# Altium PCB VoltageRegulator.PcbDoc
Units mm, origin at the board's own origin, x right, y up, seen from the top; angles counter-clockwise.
Board outline 49.88 x 50.04 mm, 2 copper layers (Top Layer, Bottom Layer); 35 components, 18 nets, 75 pads, 1 vias.
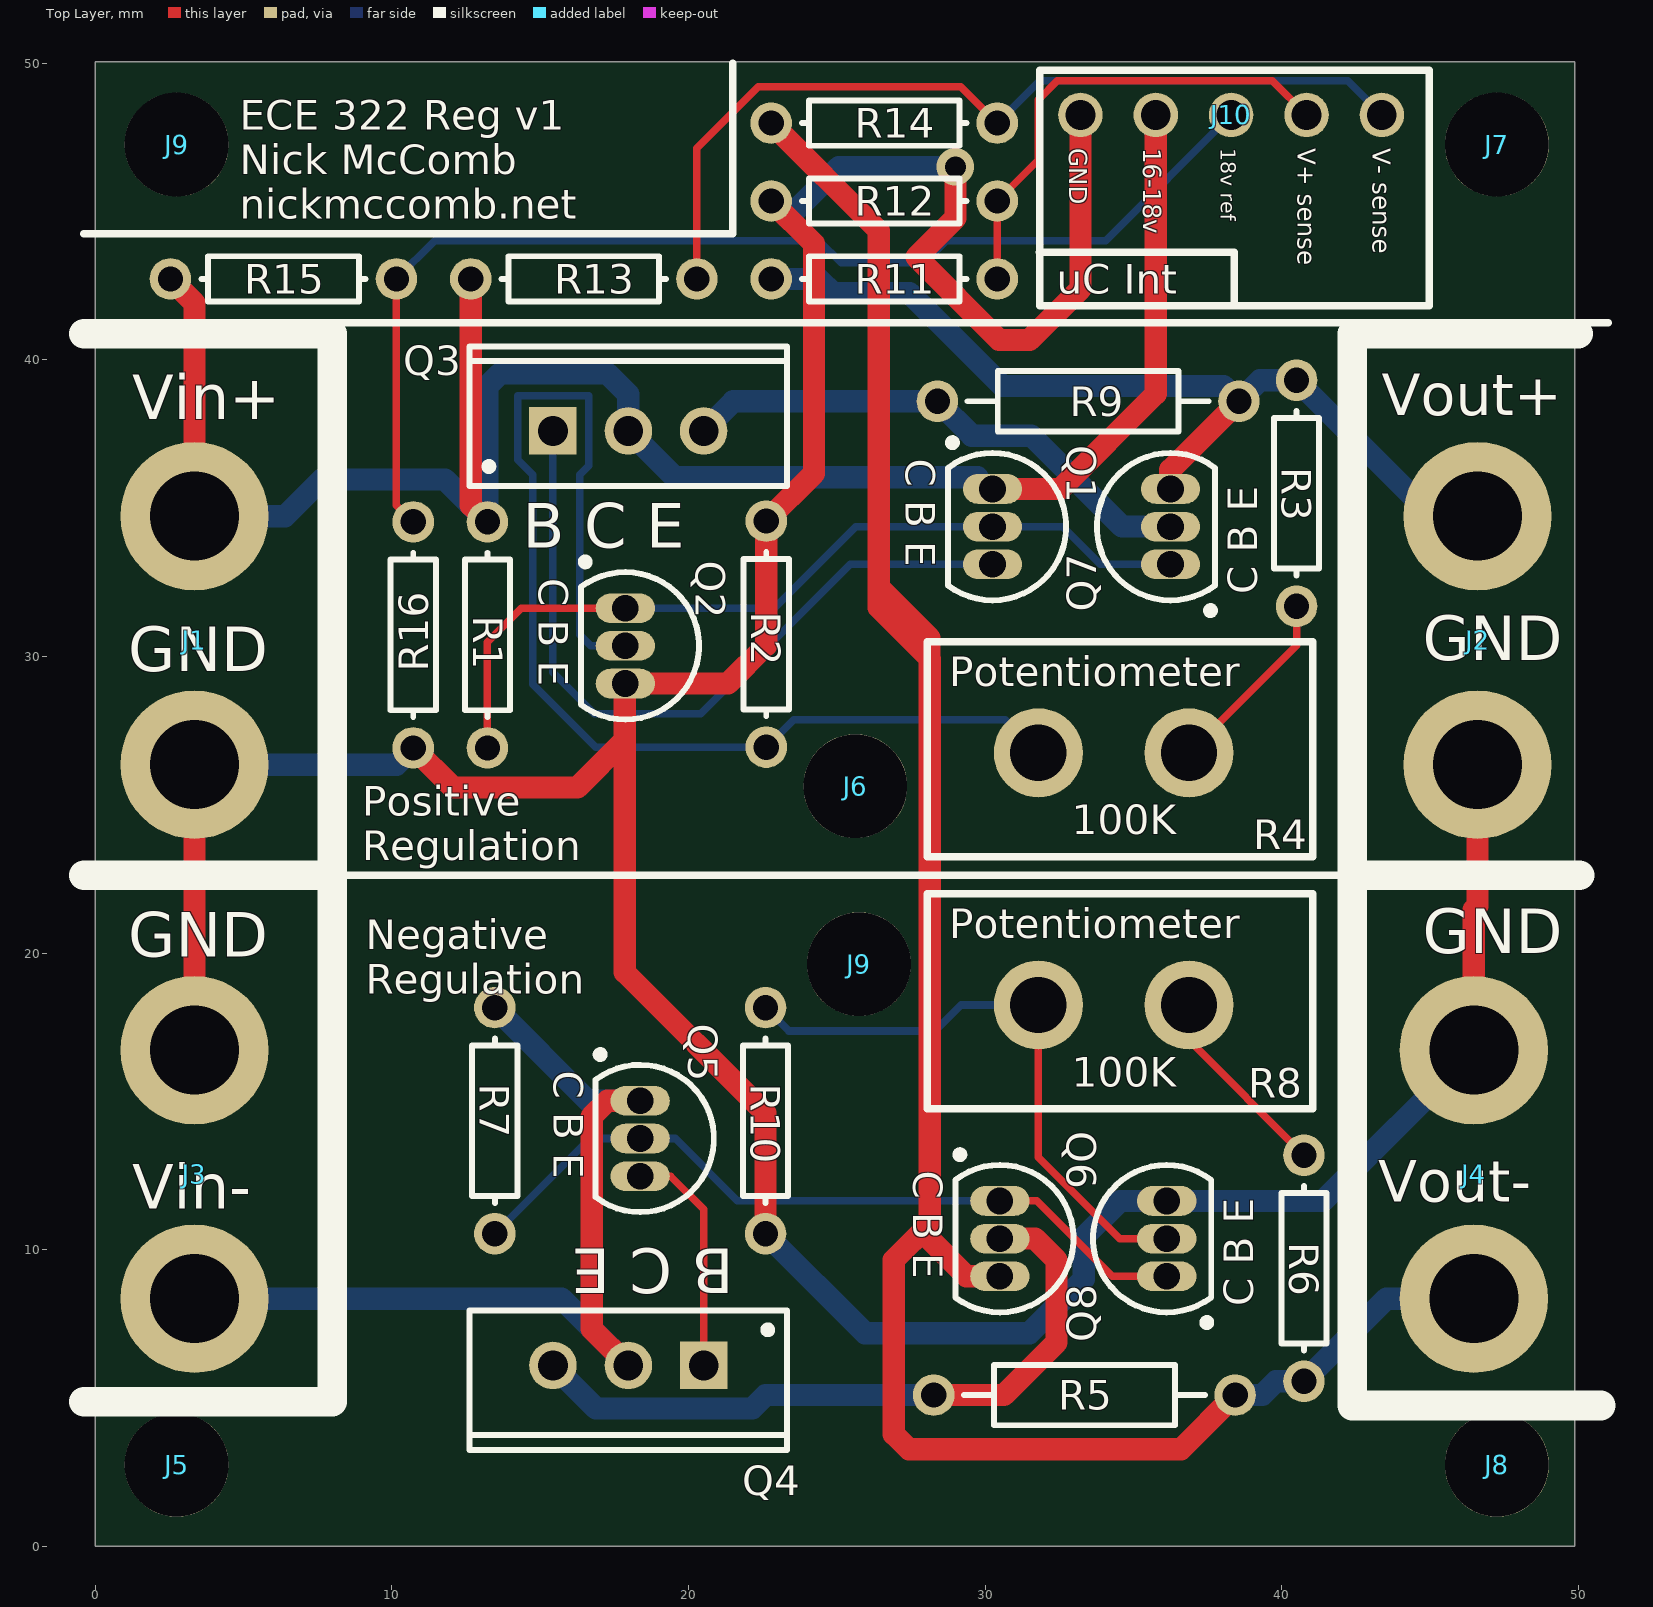
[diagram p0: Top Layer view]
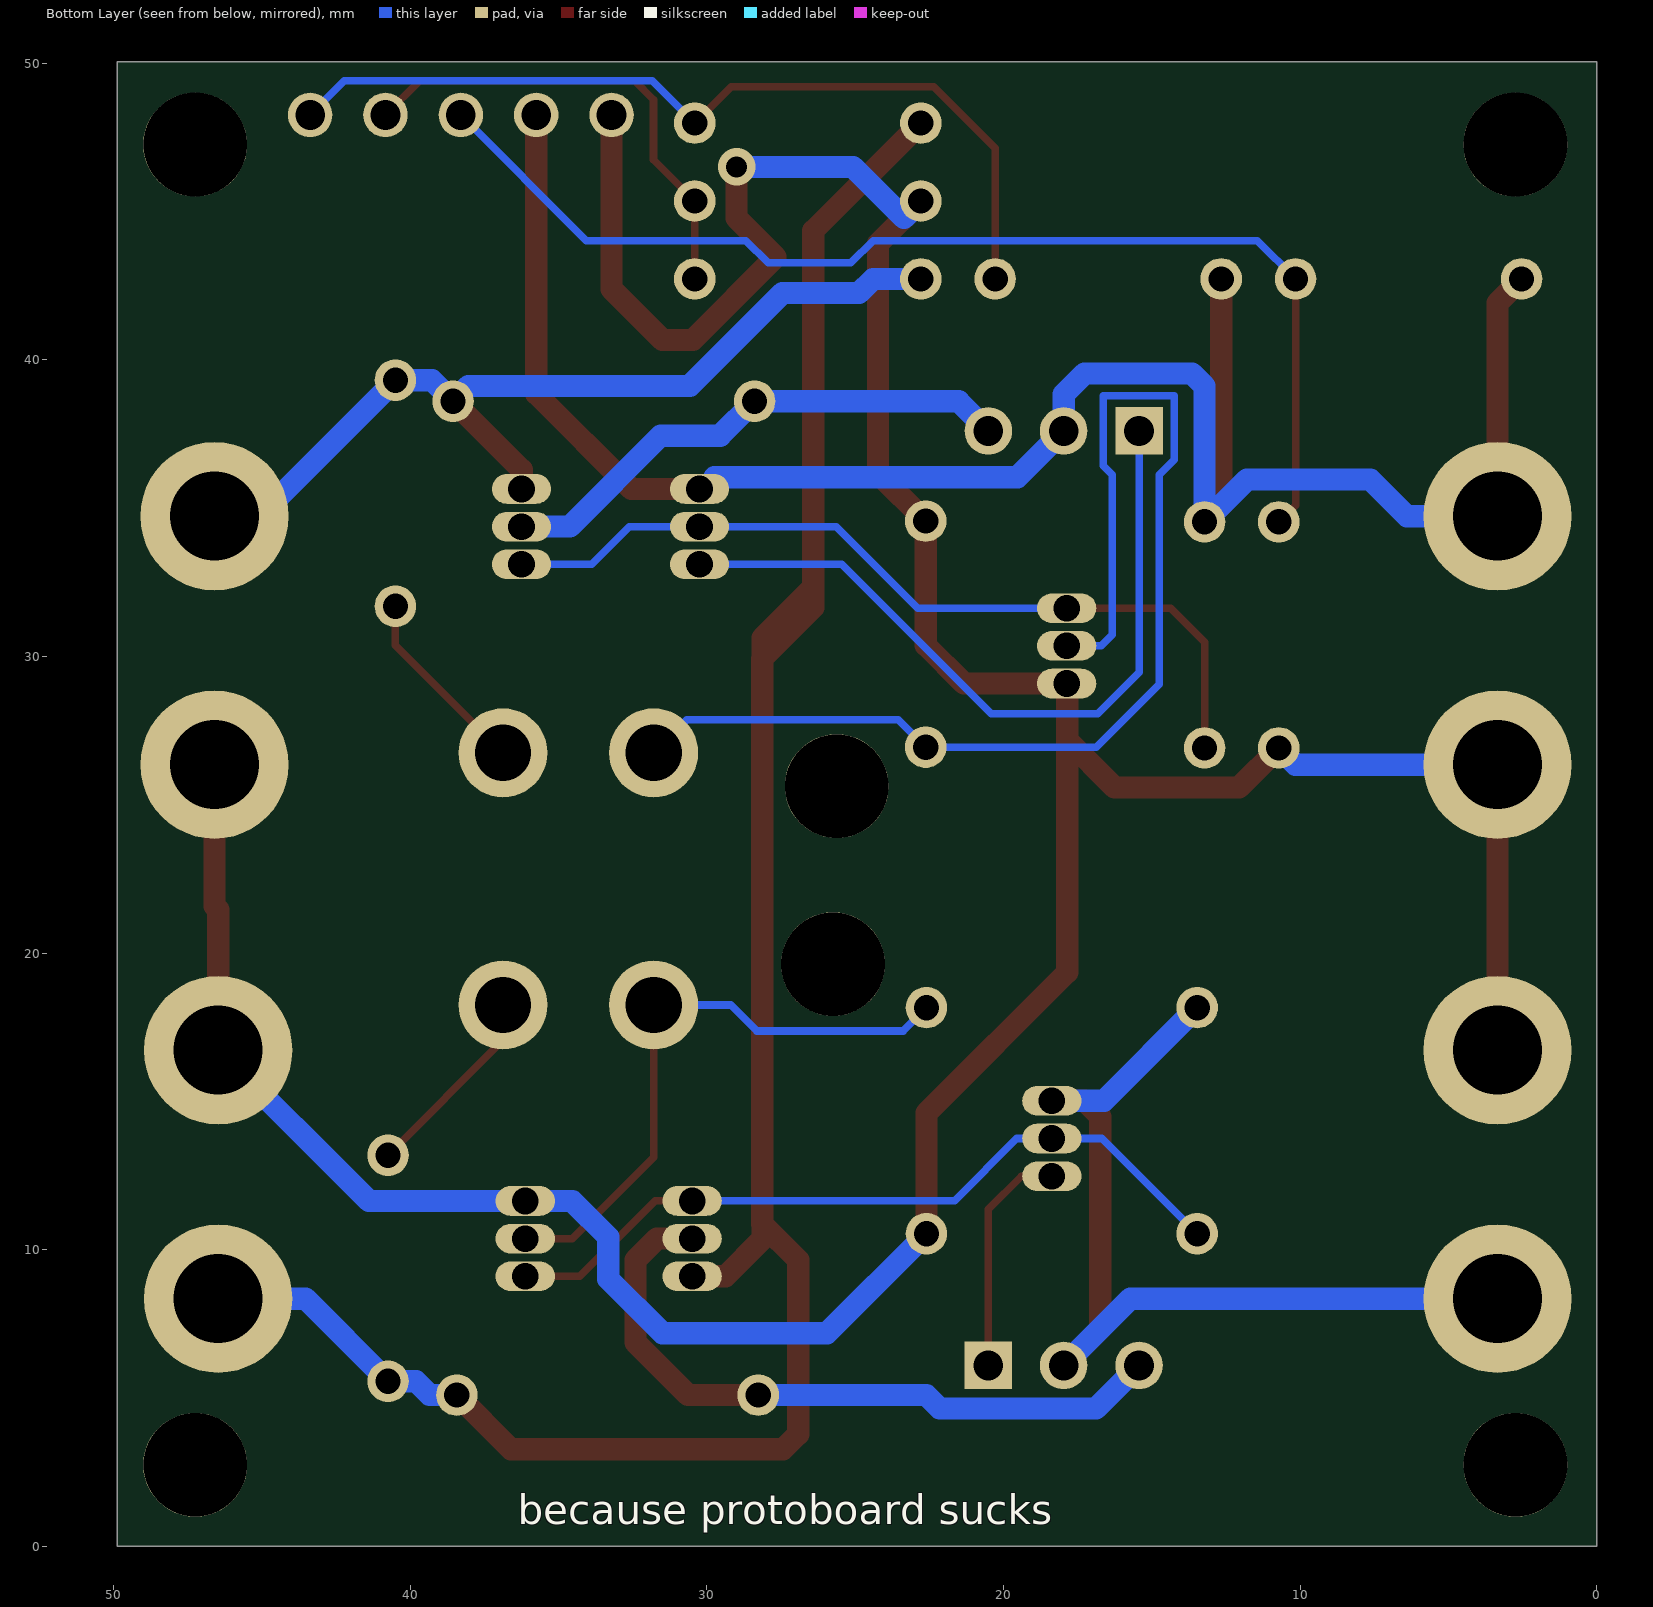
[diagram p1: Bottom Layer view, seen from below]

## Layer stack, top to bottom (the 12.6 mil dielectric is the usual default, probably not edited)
Top Solder: solder mask 0.0102, Solder Resist, Dk 3.5
Top Layer: signal copper 0.0356
Dielectric 1: dielectric 0.32, FR-4, Dk 4.8
Bottom Layer: signal copper 0.0356
Bottom Solder: solder mask 0.0102, Solder Resist, Dk 3.5

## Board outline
0,0 49.875,0 49.875,50.038 0,50.038

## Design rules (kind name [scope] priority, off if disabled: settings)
Clearance [All] p1: gap=0.254
PolygonConnect [All] p1: connectstyle=Relief reliefconductorwidth=0.254 reliefentries=4 polygonreliefangle="90 Angle" airgapwidth=0.254
RoutingVias [All] p1: holewidth=0.711 width=1.27 viastyle="Through Hole" minholewidth=0.711 minwidth=1.27 maxholewidth=0.711 maxwidth=1.27
SolderMaskExpansion [All] p1: expansion=0.102
Width "Power Traces" [(InNet('Q3_EMITTER') OR InNet('V_RECTIFIED') OR InNet('V_REGULATED') OR InNet('GND')) OR (InNet('Q4_EMITTER') OR InNet('V-_RECTIFIED') OR InNet('V-_REGULATED'))] p1: maxlimit=0.75 minlimit=0.75 preferedwidth=0.75
Width [All] p2: maxlimit=0.254 minlimit=0.254 preferedwidth=0.254
30 further rules are at their usual default settings.

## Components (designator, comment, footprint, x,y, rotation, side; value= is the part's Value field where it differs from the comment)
J1 "Power I/O" "POWER CONNECTIONS" 3.35,34.725 r180 top
J2 "Power I/O" "POWER CONNECTIONS" 46.6,34.725 r180 top
J3 "Power I/O" "POWER CONNECTIONS" 3.35,8.35 r0 top
J4 "Power I/O" "POWER CONNECTIONS" 46.475,8.35 r0 top
J5 "Mounting Hole" "Mounting Hole" 2.75,2.75 r0 top locked
J6 "Mounting Hole" "Mounting Hole" 25.625,25.625 r0 top
J7 "Mounting Hole" "Mounting Hole" 47.25,47.25 r0 top locked
J8 "Mounting Hole" "Mounting Hole" 47.25,2.75 r0 top locked
J9 "Mounting Hole" "Mounting Hole" 2.75,47.25 r0 top
J9 "Mounting Hole" "Mounting Hole" 25.75,19.625 r0 top
J10 "uC Interface" "UC INTERFACE" 33.215,48.25 r0 top
Q1 "2N4401" "TO-92A - BJT" 30.25,34.375 r180 top
Q2 "2N4401" "TO-92A - BJT" 17.875,30.355 r180 top
Q3 "TIP29C" TO-220AB 17.975,37.6 r0 top
Q4 "PNP - TIP30" TO-220AB 17.975,6.1 r180 top
Q5 "PNP - 2N4403" "TO-92A - BJT" 18.375,13.75 r180 top
Q6 "PNP - 2N4403" "TO-92A - BJT" 30.5,10.375 r180 top
Q7 "2N4401" "TO-92A - BJT" 36.25,34.375 r0 top
Q8 "PNP - 2N4403" "TO-92A - BJT" 36.125,10.375 r0 top
R1 "Res1" AXIAL-0.3 13.225,30.725 r90 top
R2 "Res1" AXIAL-0.3 22.625,30.75 r270 top
R3 "Res1" AXIAL-0.3 40.5,35.5 r90 top
R4 "Res Adj1" "POT CONNECTIONS" 31.795,26.75 r0 top
R5 "Res1" AXIAL-0.4 33.35,5.1 r0 top
R6 "Res1" AXIAL-0.3 40.75,9.375 r270 top
R7 "Res1" AXIAL-0.3 13.475,14.35 r90 top
R8 "Res Adj1" "POT CONNECTIONS" 31.795,18.25 r0 top
R9 "Res1" AXIAL-0.4 33.475,38.6 r0 top
R10 "Res1" AXIAL-0.3 22.6,14.35 r90 top
R11 "Res1" AXIAL-0.3 26.6,42.725 r180 top
R12 "Res1" AXIAL-0.3 26.6,45.35 r0 top
R13 "Res1" AXIAL-0.3 16.475,42.725 r180 top
R14 "Res1" AXIAL-0.3 26.6,47.975 r0 top
R15 "Res1" AXIAL-0.3 6.35,42.725 r0 top
R16 "Res1" AXIAL-0.3 10.725,30.725 r270 top

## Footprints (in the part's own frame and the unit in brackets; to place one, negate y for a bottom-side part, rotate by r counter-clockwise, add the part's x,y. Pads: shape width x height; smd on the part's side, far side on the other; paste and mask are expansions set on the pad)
AXIAL-0.3 [mm] "Axial Device, Thru-Hole; 2 Leads; 0.3 in Pin Spacing"
  round 1.4 hole 0.85: 1(-3.81,0) 2(3.81,0)
  silkscreen extent -2.77,-0.76 2.77,0.76
AXIAL-0.4 [mm] "Axial Device, Thru-Hole; 2 Leads; 0.4 in Pin Spacing"
  round 1.4 hole 0.85: 1(-5.08,0) 2(5.08,0)
  silkscreen extent -4.06,-1.02 4.06,1.02
"Mounting Hole" [mm]
  round 3.5 hole 3.5: A(0,0)
"POT CONNECTIONS" [mm] "Connection for an external potentiometer"
  round 3 hole 1.9: 1(0,0) 2(5.08,0)
  silkscreen extent -3.75,-3.5 9.25,3.75
"POWER CONNECTIONS" [mm]
  round 5 hole 3: 1(0,0) 2(0,8.375)
"TO-92A - BJT" [mm] "TO, Flat Index; 3 In-Line, Axial Leads; Body Dia. 4.5mm; Leads 0.51 x 0.48 mm (max)"
  oval 2x1 hole 0.9: 1(0,-1.27) 2(0,0) 3(0,1.27)
  silkscreen extent -2.48,-2.95 1.5,2.48, body extent -2.48,-2.5 1.5,2.5, height 6.86
TO-220AB [mm] "TO, Thru-Hole, Vertical, Heatsink Mounted; 3 In-Line Leads; Pitch 2.54 mm"
  rect 1.6x1.6 hole 1: 1(-2.54,0)
  round 1.6 hole 1: 2(0,0) 3(2.54,0)
  silkscreen extent -5.35,-1.85 5.35,2.85, body extent -5.4,-1.9 5.4,2.9, height 19.3
"UC INTERFACE" [mm] "uC Interface"
  round 1.5 hole 1: 1(0,0) 2(2.54,0) 3(5.08,0) 4(7.62,0) 5(10.16,0)
  silkscreen extent -1.38,-6.43 11.75,1.5

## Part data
Q1 Q2 Q3 Q7: "NPN General Purpose Amplifier"
Q4 Q5 Q6 Q8: "PNP Bipolar Transistor"
R1 R2 R3 R5 R6 R7 R9 R10 R11 R12 R13 R14 R15 R16: "Resistor"
R4 R8: "Variable Resistor"

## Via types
v1: diameter 1.27, hole 0.711, Top Layer to Bottom Layer, 1 vias

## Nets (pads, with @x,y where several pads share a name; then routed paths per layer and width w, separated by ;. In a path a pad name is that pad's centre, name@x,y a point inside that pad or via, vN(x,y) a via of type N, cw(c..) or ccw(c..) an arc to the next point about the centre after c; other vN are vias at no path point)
GND: J1.2 J2.2 J3.2 J4.2 J10.1 Q2.3 Q8.3 R2.1 R10.1 R12.1 R16.2 | length 131.4
  Top Layer w0.75: J3.2 J1.2 ; R16.2 12.062,25.578 16.256,25.578 17.856,27.178 ; R10.1 22.6,14.611 17.856,19.355 17.856,27.178 ; R12.1 24.232,43.908 24.232,36.167 R2.1 22.625,30.374 21.336,29.085 Q2.3 17.856,29.085 17.856,27.178 ; v1(29,46.5) 29,44.773 27.686,43.459 30.48,40.665 31.496,40.665 33.215,42.384 J10.1 ; J4.2 46.475,21.463 46.6,21.588 J2.2
  Bottom Layer w0.75: J1.2 10.16,26.35 R16.2 ; R10.1 25.952,7.188 31.496,7.188 33.325,9.017 33.325,10.426 34.544,11.645 Q8.3 41.395,11.645 J4.2 ; R12.1 23.36,44.78 25.08,46.5 v1(29,46.5)
NetJ10_3: J10.3 R15.2 R16.1 | length 39.5
  Top Layer w0.254: R15.2 10.16,35.1 R16.1
  Bottom Layer w0.254: R15.2 11.453,44.018 24.397,44.018 25.151,43.264 27.941,43.264 28.695,44.018 34.063,44.018 J10.3
NetJ10_4: J10.4 R11.1 R12.2 | length 16.4
  Top Layer w0.254: R11.1 R12.2 31.801,46.741 31.801,48.768 32.436,49.403 39.682,49.403 J10.4
NetJ10_5: J10.5 R13.1 R14.2 | length 29.9
  Top Layer w0.254: R13.1 20.285,47.133 22.352,49.2 29.185,49.2 R14.2
  Bottom Layer w0.254: R14.2 31.838,49.403 42.222,49.403 J10.5
NetQ1_2: Q1.2 Q2.1 Q7.1 R1.1 | length 28.7
  Top Layer w0.254: R1.1 13.225,30.48 14.37,31.625 Q2.1
  Bottom Layer w0.254: Q2.1 22.887,31.625 25.637,34.375 Q1.2 32.614,34.375 33.884,33.105 Q7.1
NetQ1_3: Q1.3 Q3.1 | length 25.6
  Bottom Layer w0.254: Q3.1 15.435,29.464 16.832,28.067 20.422,28.067 25.46,33.105 Q1.3
NetQ2_2: Q2.2 R2.2 R4.1 | length 40.9
  Bottom Layer w0.254: Q2.2 16.711,30.355 16.332,30.734 16.332,36.119 16.637,36.424 16.637,38.781 14.254,38.781 14.254,36.622 14.757,36.119 14.757,29.058 16.875,26.94 R2.2 23.549,27.864 30.681,27.864 R4.1
NetQ4_1: Q4.1 Q5.3 | length 7.9
  Top Layer w0.254: Q5.3 19.397,12.48 20.515,11.362 Q4.1
NetQ5_2: Q5.2 Q6.1 Q8.1 R7.1 | length 25.9
  Top Layer w0.254: Q6.1 31.75,11.645 34.29,9.105 Q8.1
  Bottom Layer w0.254: R7.1 16.685,13.75 Q5.2 19.549,13.75 21.654,11.645 Q6.1
NetQ8_2: Q8.2 R8.1 R10.2 | length 20.5
  Top Layer w0.254: R8.1 31.795,13.124 34.544,10.375 Q8.2
  Bottom Layer w0.254: R10.2 23.386,17.374 28.321,17.374 29.197,18.25 R8.1
NetR3_1: R3.1 R4.2 | length 6.4
  Top Layer w0.254: R4.2 40.5,30.375 R3.1
NetR6_1: R6.1 R8.2 | length 6.7
  Top Layer w0.254: R8.2 36.875,17.06 R6.1
Q3_EMITTER: Q3.3 Q7.2 R9.1 | length 17.9
  Bottom Layer w0.75: Q3.3 21.515,38.6 R9.1 29.555,37.44 31.556,37.44 34.62,34.375 Q7.2
Q4_EMITTER: Q4.3 Q6.2 R5.1 | length 23.5
  Top Layer w0.75: R5.1 30.632,5.1 32.41,6.878 32.41,9.652 31.687,10.375 Q6.2
  Bottom Layer w0.75: Q4.3 16.887,4.648 22.154,4.648 22.606,5.1 R5.1
V-_RECTIFIED: J3.1 Q4.2 Q5.1 R7.2 | length 32.5
  Top Layer w0.75: Q4.2 16.739,7.336 16.739,14.487 17.272,15.02 Q5.1
  Bottom Layer w0.75: J3.1 15.725,8.35 Q4.2 ; R7.2 16.615,15.02 Q5.1
V-_REGULATED: J4.1 Q6.3 R5.2 R6.2 R14.1 | length 94.4
  Top Layer w0.75: R14.1 26.416,44.349 26.416,32.334 ; Q6.3 29.376,9.105 28.125,10.356 28.125,18.636 28.129,18.64 28.129,30.621 26.416,32.334 ; R5.2 36.607,3.277 27.432,3.277 26.924,3.785 26.924,9.652 28.143,10.871 28.143,29.921 26.416,31.648 26.416,32.334
  Bottom Layer w0.75: R5.2 39.345,5.1 39.81,5.565 R6.2 43.535,8.35 J4.1
V_RECTIFIED: J1.1 J10.2 Q1.1 Q3.2 R1.2 R13.2 R15.1 | length 68.3
  Top Layer w0.75: R15.1 3.35,41.915 J1.1 ; R13.2 12.665,35.095 R1.2 ; Q1.1 32.546,35.645 35.755,38.854 J10.2
  Bottom Layer w0.75: J1.1 6.401,34.725 7.642,35.966 11.794,35.966 R1.2 13.225,39.116 13.646,39.537 17.272,39.537 17.975,38.834 Q3.2 19.532,36.043 29.743,36.043 29.743,35.645 Q1.1
V_REGULATED: J2.1 Q7.3 R3.2 R9.2 R11.2 | length 31.6
  Top Layer w0.75: Q7.3 36.246,35.645 36.246,36.291 R9.2
  Bottom Layer w0.75: R11.2 24.395,42.725 24.872,42.248 27.45,42.248 30.582,39.116 38.039,39.116 R9.2 39.265,39.31 R3.2 45.085,34.725 J2.1
pads on no net: J5.A J6.A J7.A J8.A J9.A

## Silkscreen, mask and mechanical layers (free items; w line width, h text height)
Top Overlay:
  lines w0.254: -0.375,44.25 21.5,44.25 21.5,49.75 21.5,50 ; 0,41.25 51,41.25 ; 5.25,22.625 44.375,22.625
  lines w1: -0.375,4.875 8,4.875 8,22.625 ; -0.375,22.625 8,22.625 ; -0.375,40.875 8,40.875 8,22.625 ; 42.375,22.5 42.375,4.75 50.75,4.75 ; 50,40.875 42.375,40.875 42.375,22.625 50.038,22.625
  text "ECE 322 Reg v1 / Nick McComb / nickmccomb.net" at 4.875,44.75 h1
  text "Vout+" at 43.375,38.125 h1.4
  text "Vin+" at 1.25,38 h1.5
  text "GND" at 44.75,29.875 h1.5
  text "GND" at 1.125,29.5 h1.5
  text "Positive / Regulation" at 9,23.125 h1
  text "GND" at 44.75,20 h1.5
  text "GND" at 1.125,19.875 h1.5
  text "Negative / Regulation" at 9.125,18.625 h1
  text "Vout-" at 43.25,11.625 h1.4
  text "Vin-" at 1.25,11.375 h1.5
Bottom Overlay:
  text "because protoboard sucks" at 36.375,0.75 h1
Mechanical 1:
  lines w0.254: 0,0 0,50 49.875,50 49.875,0 0,0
